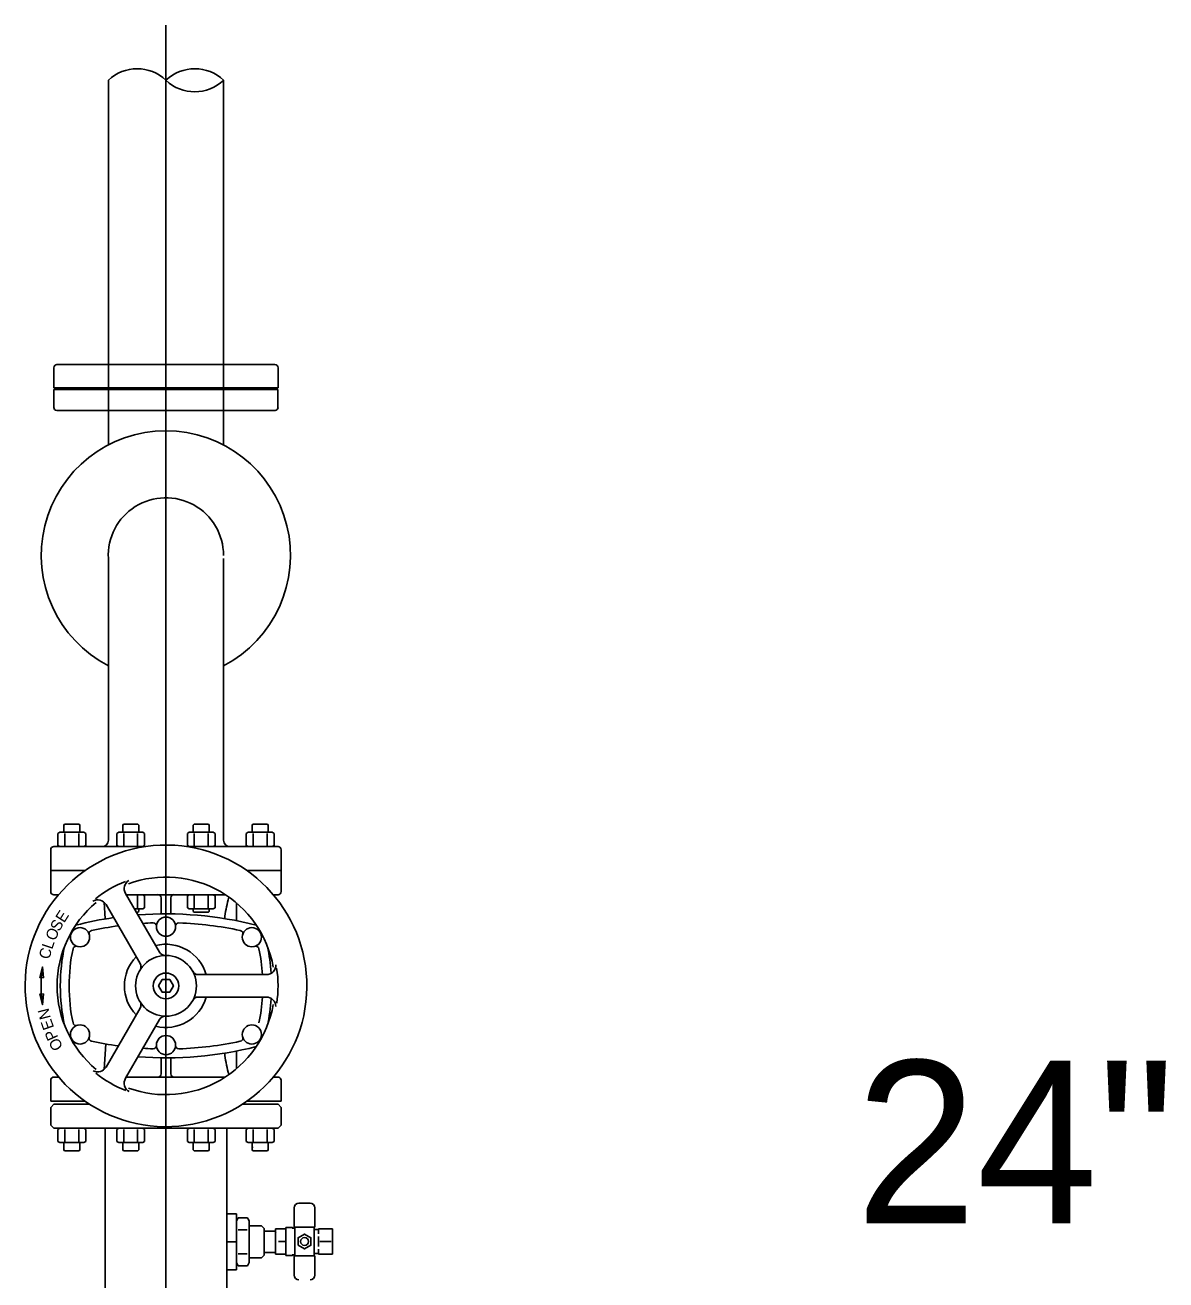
# Model space of a CAD drawing. Extents: x -1680 to 1155, y -802 to 799.
# Drawn here: x 477.9 to 526.9, y -421.5 to -367.6 of the extents above; entities that cross this region are included whole.
import ezdxf

# ---------------------------------------------------------------- set-up
doc = ezdxf.new("R2010")
doc.units = 0
doc.layers.add('Misc CnstDet(22)', color=7, linetype='Continuous')

msp = doc.modelspace()

# ---------------------------------------------------------------- linework, layer by layer
at = {"layer": 'Misc CnstDet(22)'}
for p, q in [((483.911, -491.28), (483.911, -367.568)), ((481.437, -376.477), (481.437, -369.941)), ((486.393, -376.477), (486.393, -369.941)), ((481.437, -376.477), (481.437, -385.627)), ((486.393, -376.477), (486.393, -385.631)), ((479.089, -382.307), (479.089, -383.174)), ((479.229, -382.167), (481.424, -382.167)), ((487.674, -382.167), (481.424, -382.167)), ((487.674, -382.167), (488.594, -382.167)), ((488.733, -382.307), (488.733, -383.174)), ((479.089, -383.174), (486.247, -383.174)), ((486.247, -383.174), (488.733, -383.174)), ((479.092, -383.242), (479.092, -384.014)), ((479.092, -383.242), (486.101, -383.242)), ((486.101, -383.242), (488.731, -383.242)), ((488.731, -383.242), (488.731, -384.014)), ((479.22, -384.142), (481.169, -384.142)), ((486.661, -384.142), (481.169, -384.142)), ((488.603, -384.142), (486.654, -384.142)), ((481.437, -399.574), (481.437, -390.513)), ((486.393, -399.574), (486.393, -390.513)), ((481.437, -402.632), (481.437, -399.574)), ((486.393, -402.632), (486.393, -399.574)), ((479.555, -401.944), (479.522, -401.977)), ((479.522, -401.977), (479.522, -402.291)), ((479.555, -401.944), (480.177, -401.944)), ((480.177, -401.944), (480.21, -401.977)), ((480.21, -401.977), (480.21, -402.291)), ((482.088, -401.944), (482.055, -401.977)), ((482.055, -401.977), (482.055, -402.291)), ((482.088, -401.944), (482.71, -401.944)), ((482.71, -401.944), (482.743, -401.977)), ((482.743, -401.977), (482.743, -402.291)), ((485.12, -401.944), (485.087, -401.977)), ((485.087, -401.977), (485.087, -402.291)), ((485.12, -401.944), (485.742, -401.944)), ((485.742, -401.944), (485.775, -401.977)), ((485.775, -401.977), (485.775, -402.291)), ((487.653, -401.944), (487.62, -401.977)), ((487.62, -401.977), (487.62, -402.291)), ((487.653, -401.944), (488.275, -401.944)), ((488.275, -401.944), (488.308, -401.977)), ((488.308, -401.977), (488.308, -402.291)), ((479.27, -402.337), (479.35, -402.291)), ((479.27, -402.337), (479.27, -402.862)), ((479.35, -402.291), (480.382, -402.291)), ((479.568, -402.338), (479.568, -402.86)), ((480.164, -402.338), (480.164, -402.86)), ((480.462, -402.337), (480.382, -402.291)), ((480.462, -402.337), (480.462, -402.862)), ((481.803, -402.337), (481.883, -402.291)), ((481.803, -402.337), (481.803, -402.862)), ((481.883, -402.291), (482.915, -402.291)), ((482.101, -402.338), (482.101, -402.86)), ((482.697, -402.338), (482.697, -402.86)), ((482.995, -402.337), (482.915, -402.291)), ((482.995, -402.337), (482.995, -402.862)), ((484.835, -402.337), (484.915, -402.291)), ((484.835, -402.337), (484.835, -402.862)), ((484.915, -402.291), (485.947, -402.291)), ((485.133, -402.338), (485.133, -402.86)), ((485.729, -402.338), (485.729, -402.86)), ((486.027, -402.337), (485.947, -402.291)), ((486.027, -402.337), (486.027, -402.862)), ((487.368, -402.337), (487.448, -402.291)), ((487.368, -402.337), (487.368, -402.862)), ((487.448, -402.291), (488.48, -402.291)), ((487.666, -402.338), (487.666, -402.86)), ((488.262, -402.338), (488.262, -402.86)), ((488.56, -402.337), (488.48, -402.291)), ((488.56, -402.337), (488.56, -402.862)), ((478.959, -403.94), (478.959, -403.045)), ((479.097, -402.908), (483.004, -402.908)), ((479.27, -402.862), (479.35, -402.908)), ((479.35, -402.908), (480.382, -402.908)), ((480.462, -402.862), (480.382, -402.908)), ((481.803, -402.862), (481.883, -402.908)), ((481.883, -402.908), (482.915, -402.908)), ((482.995, -402.862), (482.915, -402.908)), ((484.826, -402.908), (488.733, -402.908)), ((484.835, -402.862), (484.915, -402.908)), ((484.915, -402.908), (485.947, -402.908)), ((486.027, -402.862), (485.947, -402.908)), ((487.368, -402.862), (487.448, -402.908)), ((487.448, -402.908), (488.48, -402.908)), ((488.56, -402.862), (488.48, -402.908)), ((488.871, -403.94), (488.871, -403.045)), ((478.959, -403.94), (478.959, -404.835)), ((478.959, -403.94), (480.432, -403.94)), ((478.959, -403.94), (480.432, -403.94)), ((478.959, -404.198), (478.959, -404.835)), ((487.398, -403.94), (488.871, -403.94)), ((487.398, -403.94), (488.871, -403.94)), ((488.871, -403.94), (488.871, -404.835)), ((479.097, -404.973), (479.3, -404.973)), ((479.27, -404.973), (479.27, -405.008)), ((481.304, -406.016), (481.253, -405.295)), ((483.637, -407.451), (482.176, -404.92)), ((486.467, -404.973), (482.206, -404.973)), ((482.915, -404.973), (482.206, -404.973)), ((482.697, -405.542), (482.697, -405.02)), ((482.995, -405.019), (482.915, -404.973)), ((482.995, -405.543), (482.995, -405.019)), ((483.709, -405.8), (483.709, -405.11)), ((484.122, -405.8), (484.122, -405.11)), ((484.835, -405.019), (484.915, -404.973)), ((484.835, -405.543), (484.835, -405.019)), ((484.915, -404.973), (485.947, -404.973)), ((485.133, -405.542), (485.133, -405.02)), ((485.729, -405.542), (485.729, -405.02)), ((486.027, -405.019), (485.947, -404.973)), ((486.027, -405.543), (486.027, -405.019)), ((486.944, -406.092), (486.944, -405.327)), ((488.733, -404.973), (488.53, -404.973)), ((488.56, -404.973), (488.56, -405.008)), ((482.803, -407.933), (481.341, -405.401)), ((482.915, -405.589), (482.562, -405.589)), ((482.71, -405.727), (482.642, -405.727)), ((482.71, -405.727), (482.743, -405.694)), ((482.743, -405.694), (482.743, -405.589)), ((482.995, -405.543), (482.915, -405.589)), ((484.835, -405.543), (484.915, -405.589)), ((484.915, -405.589), (485.947, -405.589)), ((485.087, -405.694), (485.087, -405.589)), ((485.12, -405.727), (485.087, -405.694)), ((485.12, -405.727), (485.742, -405.727)), ((485.742, -405.727), (485.775, -405.694)), ((485.775, -405.694), (485.775, -405.589)), ((486.027, -405.543), (485.947, -405.589)), ((485.305, -408.414), (488.228, -408.414)), ((485.305, -409.378), (488.228, -409.378)), ((482.803, -409.859), (481.341, -412.391)), ((483.637, -410.341), (482.176, -412.872)), ((481.33, -411.396), (481.253, -412.497)), ((486.944, -411.7), (486.944, -412.465)), ((483.709, -411.992), (483.709, -412.682)), ((484.122, -411.992), (484.122, -412.682)), ((479.3, -412.819), (479.097, -412.819)), ((486.467, -412.819), (482.206, -412.819)), ((488.733, -412.819), (488.53, -412.819)), ((478.959, -413.852), (478.959, -412.957)), ((488.871, -413.852), (488.871, -412.957)), ((480.432, -413.852), (478.959, -413.852)), ((478.959, -413.852), (480.432, -413.852)), ((478.959, -414.127), (479.097, -413.989)), ((480.637, -413.989), (479.097, -413.989)), ((487.193, -413.989), (488.733, -413.989)), ((488.871, -413.852), (487.398, -413.852)), ((487.398, -413.852), (488.871, -413.852)), ((488.733, -413.989), (488.871, -414.127)), ((478.959, -414.127), (478.959, -414.884)), ((488.871, -414.127), (488.871, -414.884)), ((478.959, -414.884), (479.097, -415.022)), ((479.097, -415.022), (481.162, -415.022)), ((479.27, -415.068), (479.35, -415.022)), ((479.27, -415.592), (479.27, -415.068)), ((480.382, -415.022), (479.35, -415.022)), ((479.568, -415.591), (479.568, -415.069)), ((480.164, -415.591), (480.164, -415.069)), ((480.462, -415.068), (480.382, -415.022)), ((480.462, -415.592), (480.462, -415.068)), ((483.915, -415.022), (481.162, -415.022)), ((481.299, -415.653), (481.299, -415.022)), ((481.803, -415.068), (481.883, -415.022)), ((481.803, -415.592), (481.803, -415.068)), ((482.915, -415.022), (481.883, -415.022)), ((482.101, -415.591), (482.101, -415.069)), ((482.697, -415.591), (482.697, -415.069)), ((482.995, -415.068), (482.915, -415.022)), ((482.995, -415.592), (482.995, -415.068)), ((488.733, -415.022), (483.915, -415.022)), ((484.835, -415.068), (484.915, -415.022)), ((484.835, -415.592), (484.835, -415.068)), ((485.947, -415.022), (484.915, -415.022)), ((485.133, -415.591), (485.133, -415.069)), ((485.729, -415.591), (485.729, -415.069)), ((486.027, -415.068), (485.947, -415.022)), ((486.027, -415.592), (486.027, -415.068)), ((486.531, -415.653), (486.531, -415.022)), ((487.368, -415.068), (487.448, -415.022)), ((487.368, -415.592), (487.368, -415.068)), ((488.48, -415.022), (487.448, -415.022)), ((487.666, -415.591), (487.666, -415.069)), ((488.262, -415.591), (488.262, -415.069)), ((488.56, -415.068), (488.48, -415.022)), ((488.56, -415.592), (488.56, -415.068)), ((488.871, -414.884), (488.733, -415.022)), ((479.27, -415.592), (479.35, -415.639)), ((480.462, -415.592), (480.382, -415.639)), ((481.803, -415.592), (481.883, -415.639)), ((482.995, -415.592), (482.915, -415.639)), ((484.835, -415.592), (484.915, -415.639)), ((486.027, -415.592), (485.947, -415.639)), ((487.368, -415.592), (487.448, -415.639)), ((488.56, -415.592), (488.48, -415.639)), ((480.382, -415.639), (479.35, -415.639)), ((479.522, -415.952), (479.522, -415.639)), ((479.555, -415.985), (479.522, -415.952)), ((480.177, -415.985), (479.555, -415.985)), ((480.177, -415.985), (480.21, -415.952)), ((480.21, -415.952), (480.21, -415.639)), ((481.299, -443.793), (481.299, -415.653)), ((482.915, -415.639), (481.883, -415.639)), ((482.055, -415.952), (482.055, -415.639)), ((482.088, -415.985), (482.055, -415.952)), ((482.71, -415.985), (482.088, -415.985)), ((482.71, -415.985), (482.743, -415.952)), ((482.743, -415.952), (482.743, -415.639)), ((485.947, -415.639), (484.915, -415.639)), ((485.087, -415.952), (485.087, -415.639)), ((485.12, -415.985), (485.087, -415.952)), ((485.742, -415.985), (485.12, -415.985)), ((485.742, -415.985), (485.775, -415.952)), ((485.775, -415.952), (485.775, -415.639)), ((486.531, -443.793), (486.531, -415.653)), ((488.48, -415.639), (487.448, -415.639)), ((487.62, -415.952), (487.62, -415.639)), ((487.653, -415.858), (487.62, -415.825)), ((487.653, -415.985), (487.62, -415.952)), ((488.275, -415.985), (487.653, -415.985)), ((488.275, -415.985), (488.308, -415.952)), ((488.308, -415.952), (488.308, -415.639)), ((489.873, -418.24), (489.634, -418.24)), ((489.873, -418.24), (490.113, -418.24)), ((486.944, -418.705), (486.531, -418.705)), ((486.944, -421.115), (486.944, -418.705)), ((489.427, -419.273), (489.427, -418.447)), ((490.319, -419.273), (490.319, -418.447)), ((487.024, -418.881), (486.944, -419.02)), ((487.024, -418.881), (487.414, -418.881)), ((487.026, -419.389), (487.412, -419.389)), ((487.414, -418.881), (487.494, -419.02)), ((487.457, -418.947), (487.494, -419.011)), ((487.494, -420.8), (487.494, -419.011)), ((487.494, -420.8), (487.494, -419.011)), ((488.029, -419.218), (487.494, -419.218)), ((488.138, -419.327), (488.029, -419.218)), ((488.138, -420.484), (488.138, -419.327)), ((488.621, -419.892), (488.621, -419.341)), ((489.072, -419.341), (488.621, -419.341)), ((489.072, -419.341), (489.002, -419.341)), ((489.072, -419.291), (489.072, -420.493)), ((489.072, -419.291), (489.348, -419.291)), ((489.372, -419.291), (489.372, -419.291)), ((489.372, -419.341), (489.372, -419.308)), ((489.391, -419.317), (489.46, -419.317)), ((489.873, -419.273), (489.427, -419.273)), ((489.46, -419.892), (489.46, -419.273)), ((489.873, -419.273), (490.319, -419.273)), ((490.286, -419.892), (490.286, -419.273)), ((490.291, -419.376), (490.449, -419.376)), ((490.466, -419.567), (490.466, -419.341)), ((490.466, -419.341), (491.075, -419.341)), ((491.075, -419.341), (491.075, -419.892)), ((486.944, -419.91), (486.531, -419.91)), ((488.242, -419.443), (488.138, -419.446)), ((488.517, -419.443), (488.242, -419.443)), ((488.517, -419.443), (488.62, -419.446)), ((488.621, -419.892), (488.621, -420.443)), ((488.676, -419.496), (488.676, -419.496)), ((488.746, -419.892), (489.072, -419.892)), ((489.46, -419.892), (489.46, -420.511)), ((490.286, -419.892), (490.286, -420.511)), ((490.466, -419.892), (490.466, -419.679)), ((490.466, -419.892), (490.466, -420.105)), ((491.011, -419.892), (490.53, -419.892)), ((491.075, -419.892), (491.075, -420.443)), ((487.026, -420.422), (487.412, -420.422)), ((488.242, -420.368), (488.138, -420.365)), ((488.517, -420.368), (488.242, -420.368)), ((488.517, -420.368), (488.62, -420.365)), ((489.072, -420.443), (488.621, -420.443)), ((488.676, -420.421), (488.676, -420.421)), ((489.372, -420.443), (489.372, -420.476)), ((489.391, -420.467), (489.46, -420.467)), ((490.291, -420.408), (490.449, -420.408)), ((490.466, -420.217), (490.466, -420.443)), ((490.466, -420.443), (491.075, -420.443)), ((487.024, -420.939), (486.944, -420.8)), ((487.024, -420.939), (487.414, -420.939)), ((487.414, -420.939), (487.494, -420.8)), ((488.029, -420.593), (487.494, -420.593)), ((488.138, -420.484), (488.029, -420.593)), ((489.072, -420.493), (489.348, -420.493)), ((489.427, -420.511), (489.427, -421.337)), ((489.873, -420.511), (489.427, -420.511)), ((489.873, -420.511), (490.319, -420.511)), ((490.319, -420.511), (490.319, -421.337)), ((486.944, -421.115), (486.531, -421.115))]:
    msp.add_line(p, q, dxfattribs=at)
for points in [[(478.651, -408.552), (478.496, -408.54), (478.608, -408.083)], [(483.756, -408.621), (483.597, -408.896), (483.756, -409.171), (484.074, -409.171), (484.233, -408.896), (484.074, -408.621)], [(478.651, -409.24), (478.496, -409.252), (478.608, -409.709)], [(489.598, -420.051), (489.873, -420.21), (490.149, -420.051), (490.149, -419.733), (489.873, -419.574), (489.598, -419.733)]]:
    msp.add_lwpolyline(points, close=True, dxfattribs=at)
for centre, radius in [((480.22, -406.805), 0.413), ((483.915, -406.349), 0.413), ((487.61, -406.805), 0.413), ((483.915, -408.896), 1.308), ((483.915, -408.896), 0.551), ((480.22, -410.987), 0.413), ((487.61, -410.987), 0.413), ((483.915, -411.443), 0.413), ((489.873, -419.892), 0.172)]:
    msp.add_circle(centre, radius, dxfattribs=at)
for centre, radius, start, end in [((482.675, -371.247), 1.8, 46.4429, 133.4774), ((485.156, -371.248), 1.801, 46.5406, 133.539), ((485.155, -368.642), 1.797, 226.4033, 313.6763), ((479.229, -382.307), 0.139, 90, 180), ((488.594, -382.307), 0.139, 0, 90), ((479.22, -384.014), 0.129, 180, 270), ((488.603, -384.014), 0.129, 270, 0), ((483.911, -390.379), 5.358, 297.5711, 242.4959), ((483.911, -390.379), 2.478, 0.0006, 183.0872), ((481.162, -402.632), 0.275, 270, 0), ((486.668, -402.632), 0.275, 180, 270), ((483.915, -408.896), 6.057, 89.4109, 89.3632), ((479.097, -403.045), 0.138, 90, 180), ((488.733, -403.045), 0.138, 39.9587, 90), ((488.733, -403.045), 0.138, 0, 90), ((478.821, -404.198), 0.138, 0, 11.7683), ((483.915, -408.896), 4.68, 9.8969, 110.1031), ((483.915, -408.896), 4.818, 111.1733, 129.046), ((482.533, -404.713), 0.413, 121.7915, 210), ((479.097, -404.835), 0.138, 180, 270), ((483.915, -408.896), 4.68, 129.8969, 230.1031), ((480.983, -405.608), 0.413, 30, 121.3135), ((483.571, -405.11), 0.138, 0, 90), ((484.259, -405.11), 0.138, 90, 180), ((491.788, -406.542), 5.374, 165.4239, 174.2397), ((487.04, -405.33), 0.474, 148.9584, 162.6862), ((488.733, -404.835), 0.138, 270, 0), ((483.915, -421.561), 15.762, 75.7334, 94.3855), ((483.915, -421.561), 15.762, 98.2117, 104.2666), ((483.915, -421.561), 15.384, 97.6469, 101.9908), ((483.915, -421.561), 15.384, 92.0678, 93.7076), ((483.365, -406.325), 0.138, 357.4512, 92.0678), ((484.465, -406.325), 0.138, 87.9322, 182.5489), ((483.915, -421.561), 15.384, 78.0092, 87.9322), ((480.748, -406.648), 0.138, 101.9908, 196.6074), ((487.082, -406.648), 0.138, 343.3926, 78.0092), ((487.431, -408.896), 8.059, 167.8489, 192.1511), ((487.431, -408.896), 7.68, 168.0139, 180), ((480.053, -407.33), 0.138, 72.3405, 168.0139), ((483.915, -408.896), 1.79, 15.6185, 104.3815), ((483.876, -407.313), 0.275, 210, 271.4281), ((487.777, -407.33), 0.138, 11.9861, 107.6595), ((480.399, -408.896), 7.68, 3.5967, 11.9861), ((480.399, -408.896), 8.059, 3.9315, 12.1511), ((483.915, -408.896), 1.79, 135.6185, 224.3815), ((482.564, -408.071), 0.275, 328.5719, 30), ((488.228, -408.001), 0.413, 270, 1.3135), ((483.915, -408.896), 5.369, 173.2861, 186.7139), ((485.305, -408.139), 0.275, 208.5719, 270), ((483.915, -408.896), 4.818, 351.1733, 9.046), ((487.431, -408.896), 7.68, 180, 191.9861), ((482.564, -409.721), 0.275, 330, 31.4281), ((483.915, -408.896), 1.79, 255.6185, 344.3815), ((485.305, -409.653), 0.275, 90, 151.4281), ((480.399, -408.896), 7.68, 348.0139, 356.4033), ((488.228, -409.791), 0.413, 1.7915, 90), ((480.399, -408.896), 8.059, 347.8489, 356.0685), ((483.915, -408.896), 4.68, 249.8969, 350.1031), ((483.876, -410.479), 0.275, 88.5719, 150), ((480.053, -410.462), 0.138, 191.9861, 287.6595), ((480.748, -411.145), 0.138, 163.3926, 258.0092), ((483.915, -396.231), 15.384, 258.0092, 262.3531), ((483.915, -396.231), 15.384, 272.0678, 281.9908), ((487.082, -411.145), 0.138, 281.9908, 16.6074), ((483.915, -396.231), 15.762, 265.6145, 284.2666), ((483.915, -396.231), 15.384, 266.2924, 267.9322), ((483.365, -411.467), 0.138, 267.9322, 2.5489), ((484.465, -411.467), 0.138, 177.4512, 272.0678), ((491.788, -411.25), 5.374, 185.7603, 194.5761), ((479.097, -412.957), 0.138, 90, 180), ((480.983, -412.184), 0.413, 241.7915, 330), ((483.915, -408.896), 4.818, 231.1733, 249.046), ((482.533, -413.079), 0.413, 150, 241.3135), ((483.571, -412.682), 0.138, 270, 0), ((484.259, -412.682), 0.138, 180, 270), ((487.04, -412.462), 0.474, 197.3138, 211.0416), ((488.733, -412.957), 0.138, 0, 90), ((489.634, -418.447), 0.206, 90, 180), ((490.113, -418.447), 0.206, 0, 90), ((489.348, -419.315), 0.024, 27.2796, 90), ((489.391, -419.293), 0.024, 207.2796, 270), ((490.291, -419.359), 0.0172, 254.1733, 270), ((490.449, -419.359), 0.0172, 270, 0), ((489.391, -420.491), 0.024, 90, 152.7204), ((490.449, -420.425), 0.0172, 0, 90), ((489.348, -420.469), 0.024, 270, 332.7204), ((489.634, -421.337), 0.206, 180, 270), ((490.113, -421.337), 0.206, 270, 0)]:
    msp.add_arc(centre, radius, start, end, dxfattribs=at)

# ---------------------------------------------------------------- texts
for s, rotation, p in [('E', 57.3232, (479.535, -406.214)), ('O', 66.6982, (479.15, -406.989)), ('S', 62.0107, (479.329, -406.588)), ('C', 76.0732, (478.906, -407.78)), ('L', 71.3857, (479.02, -407.352)), ('N', 104.3391, (478.971, -410.273)), ('E', 109.3391, (479.112, -410.69)), ('P', 114.3391, (479.291, -411.113)), ('O', 119.3391, (479.508, -411.52))]:
    msp.add_text(s, height=0.482, rotation=rotation, dxfattribs=at).set_placement(p)
msp.add_text('24"', height=7, dxfattribs=at).set_placement((513.571, -419.109))

doc.saveas('drawing.dxf')
